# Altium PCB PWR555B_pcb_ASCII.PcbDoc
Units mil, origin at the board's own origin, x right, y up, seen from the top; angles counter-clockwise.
Board outline 3000 x 3000 mil, 4 copper layers (Top Layer, MidLayer1, MidLayer2, Bottom Layer), stack 41.2 mil thick; 56 components, 14 nets, 87 pads, 41 vias.
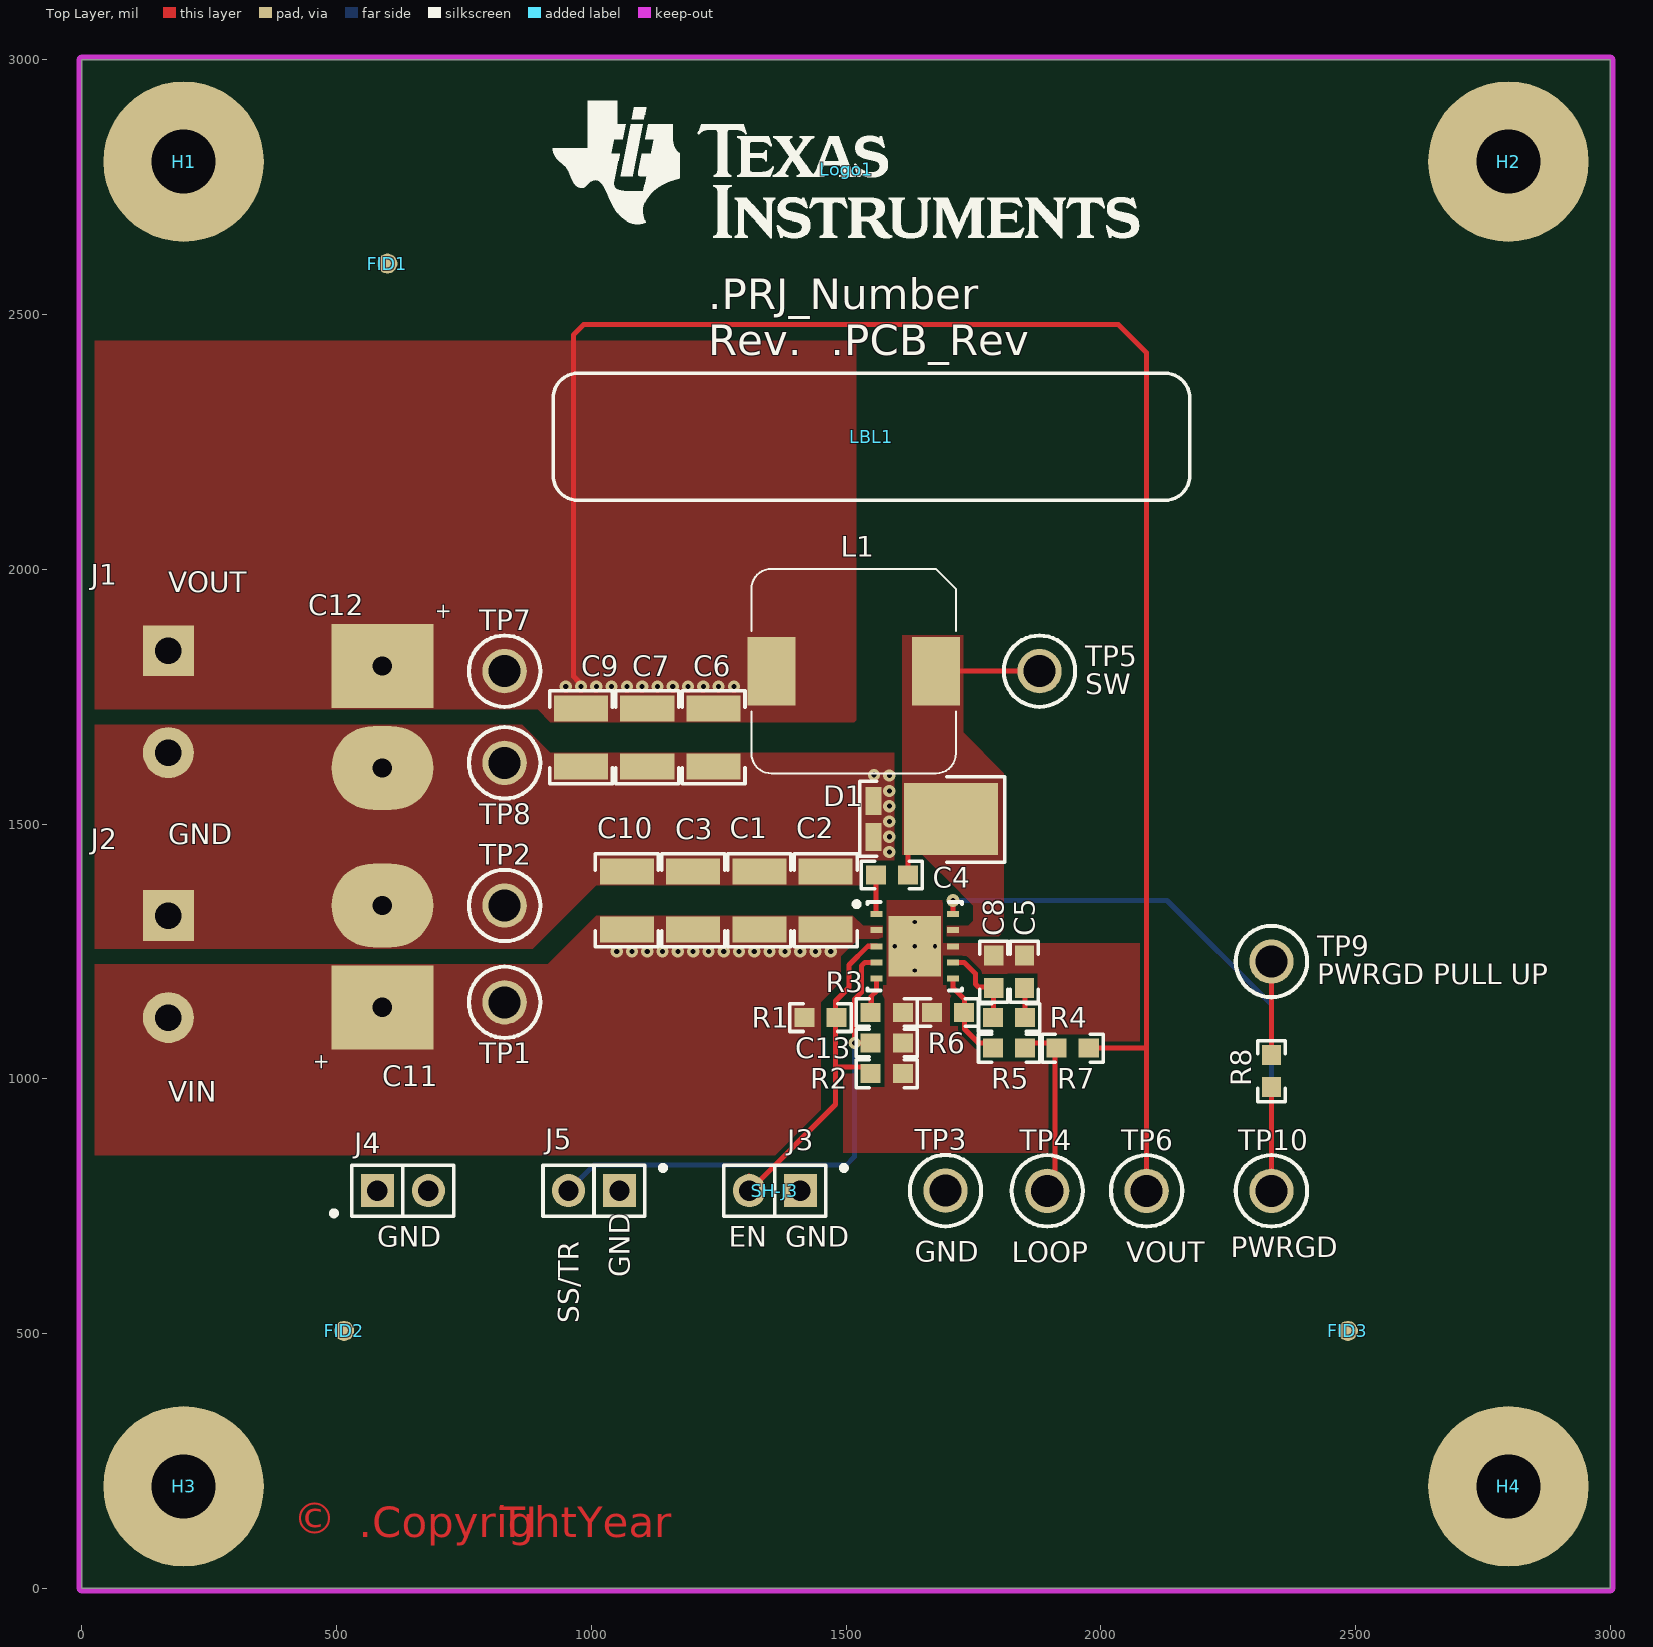
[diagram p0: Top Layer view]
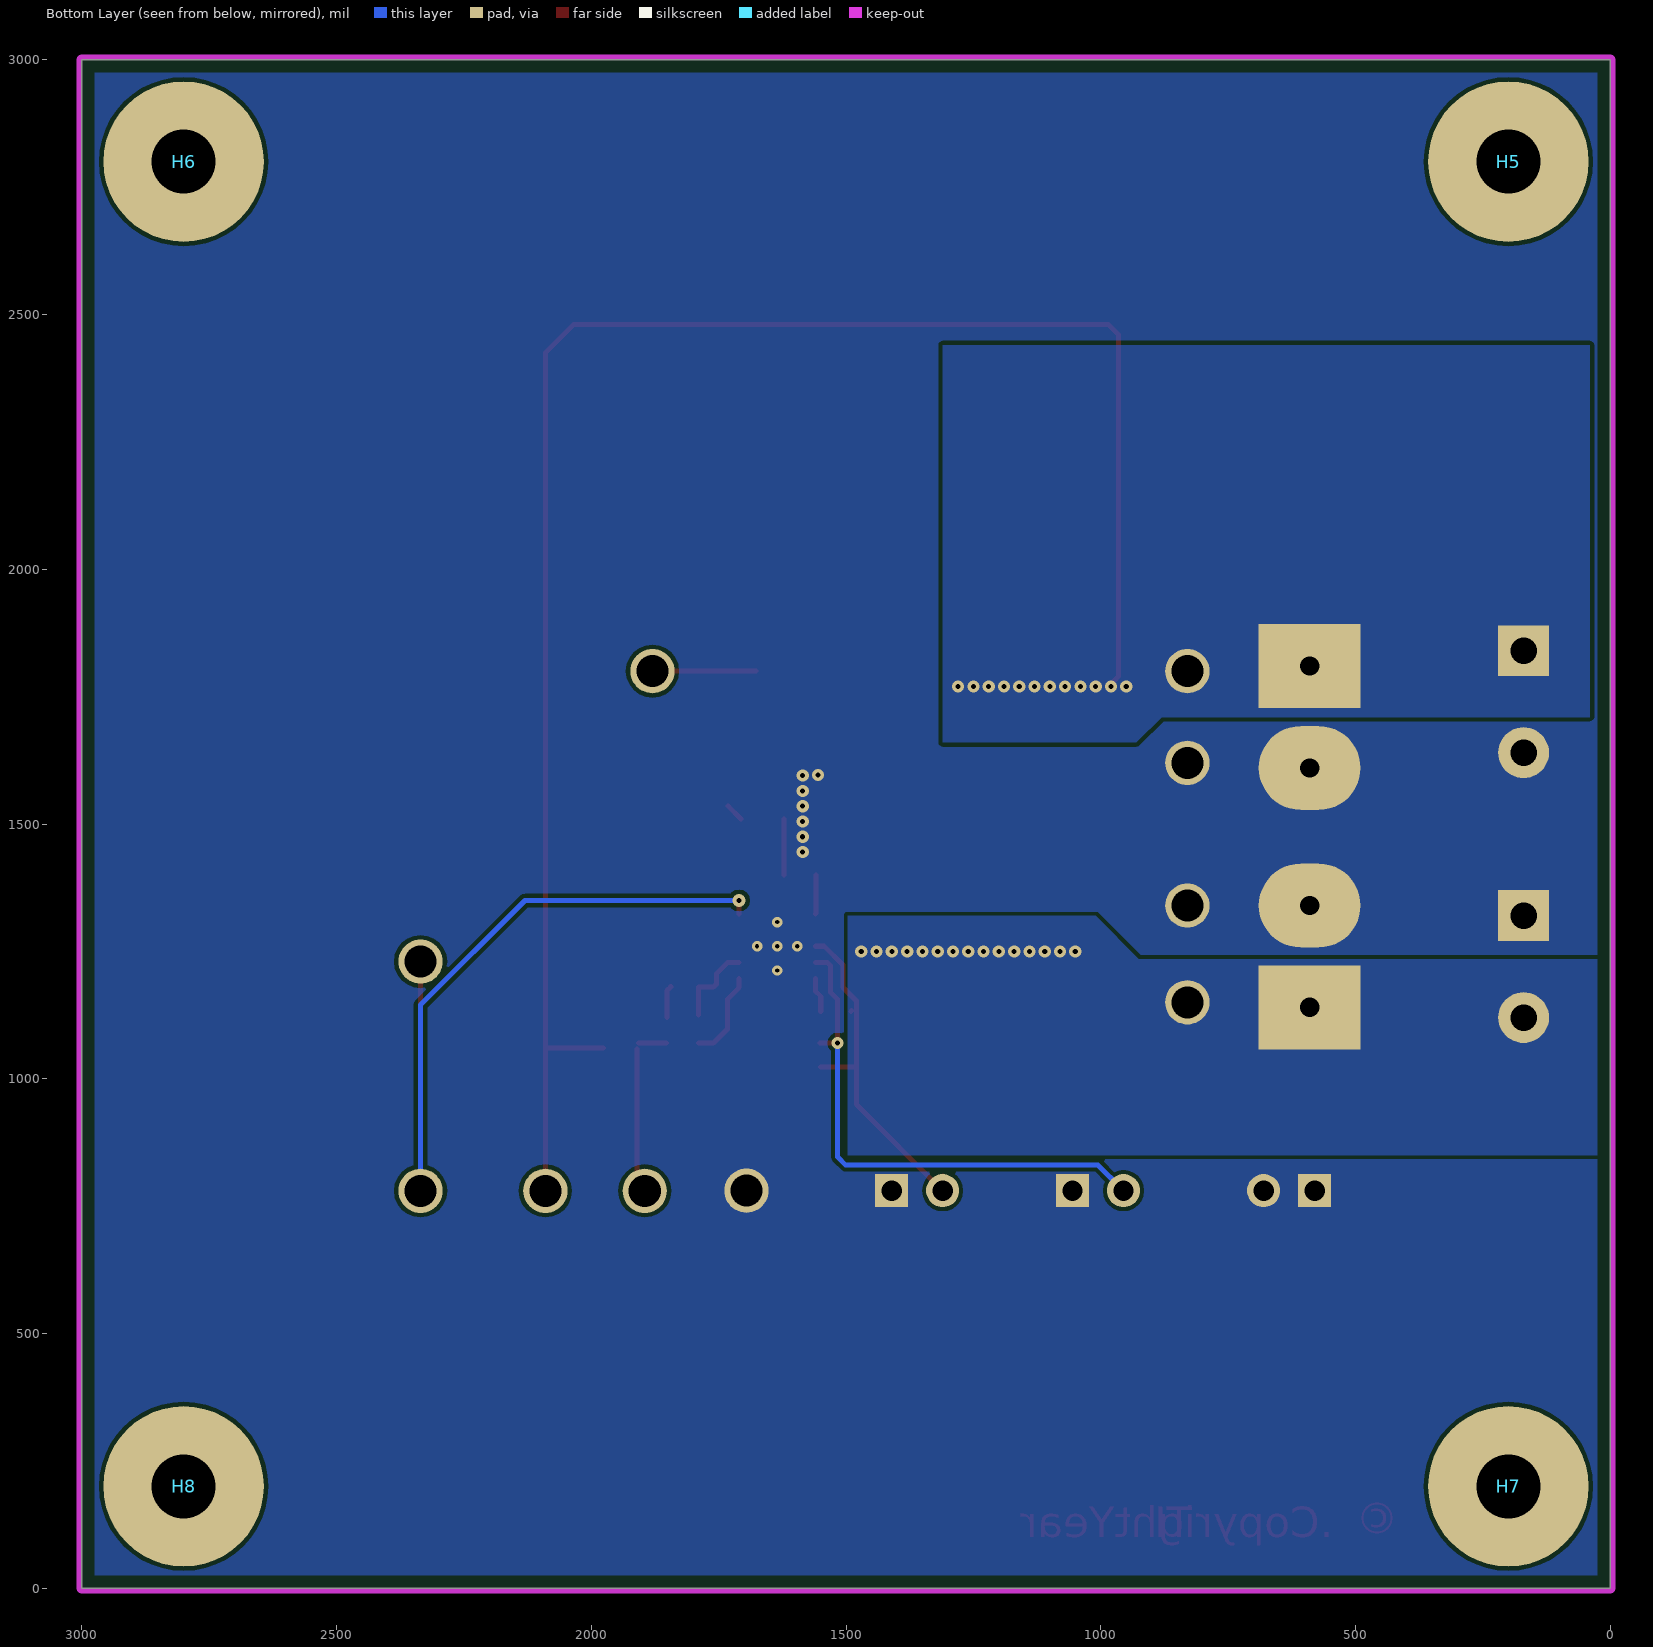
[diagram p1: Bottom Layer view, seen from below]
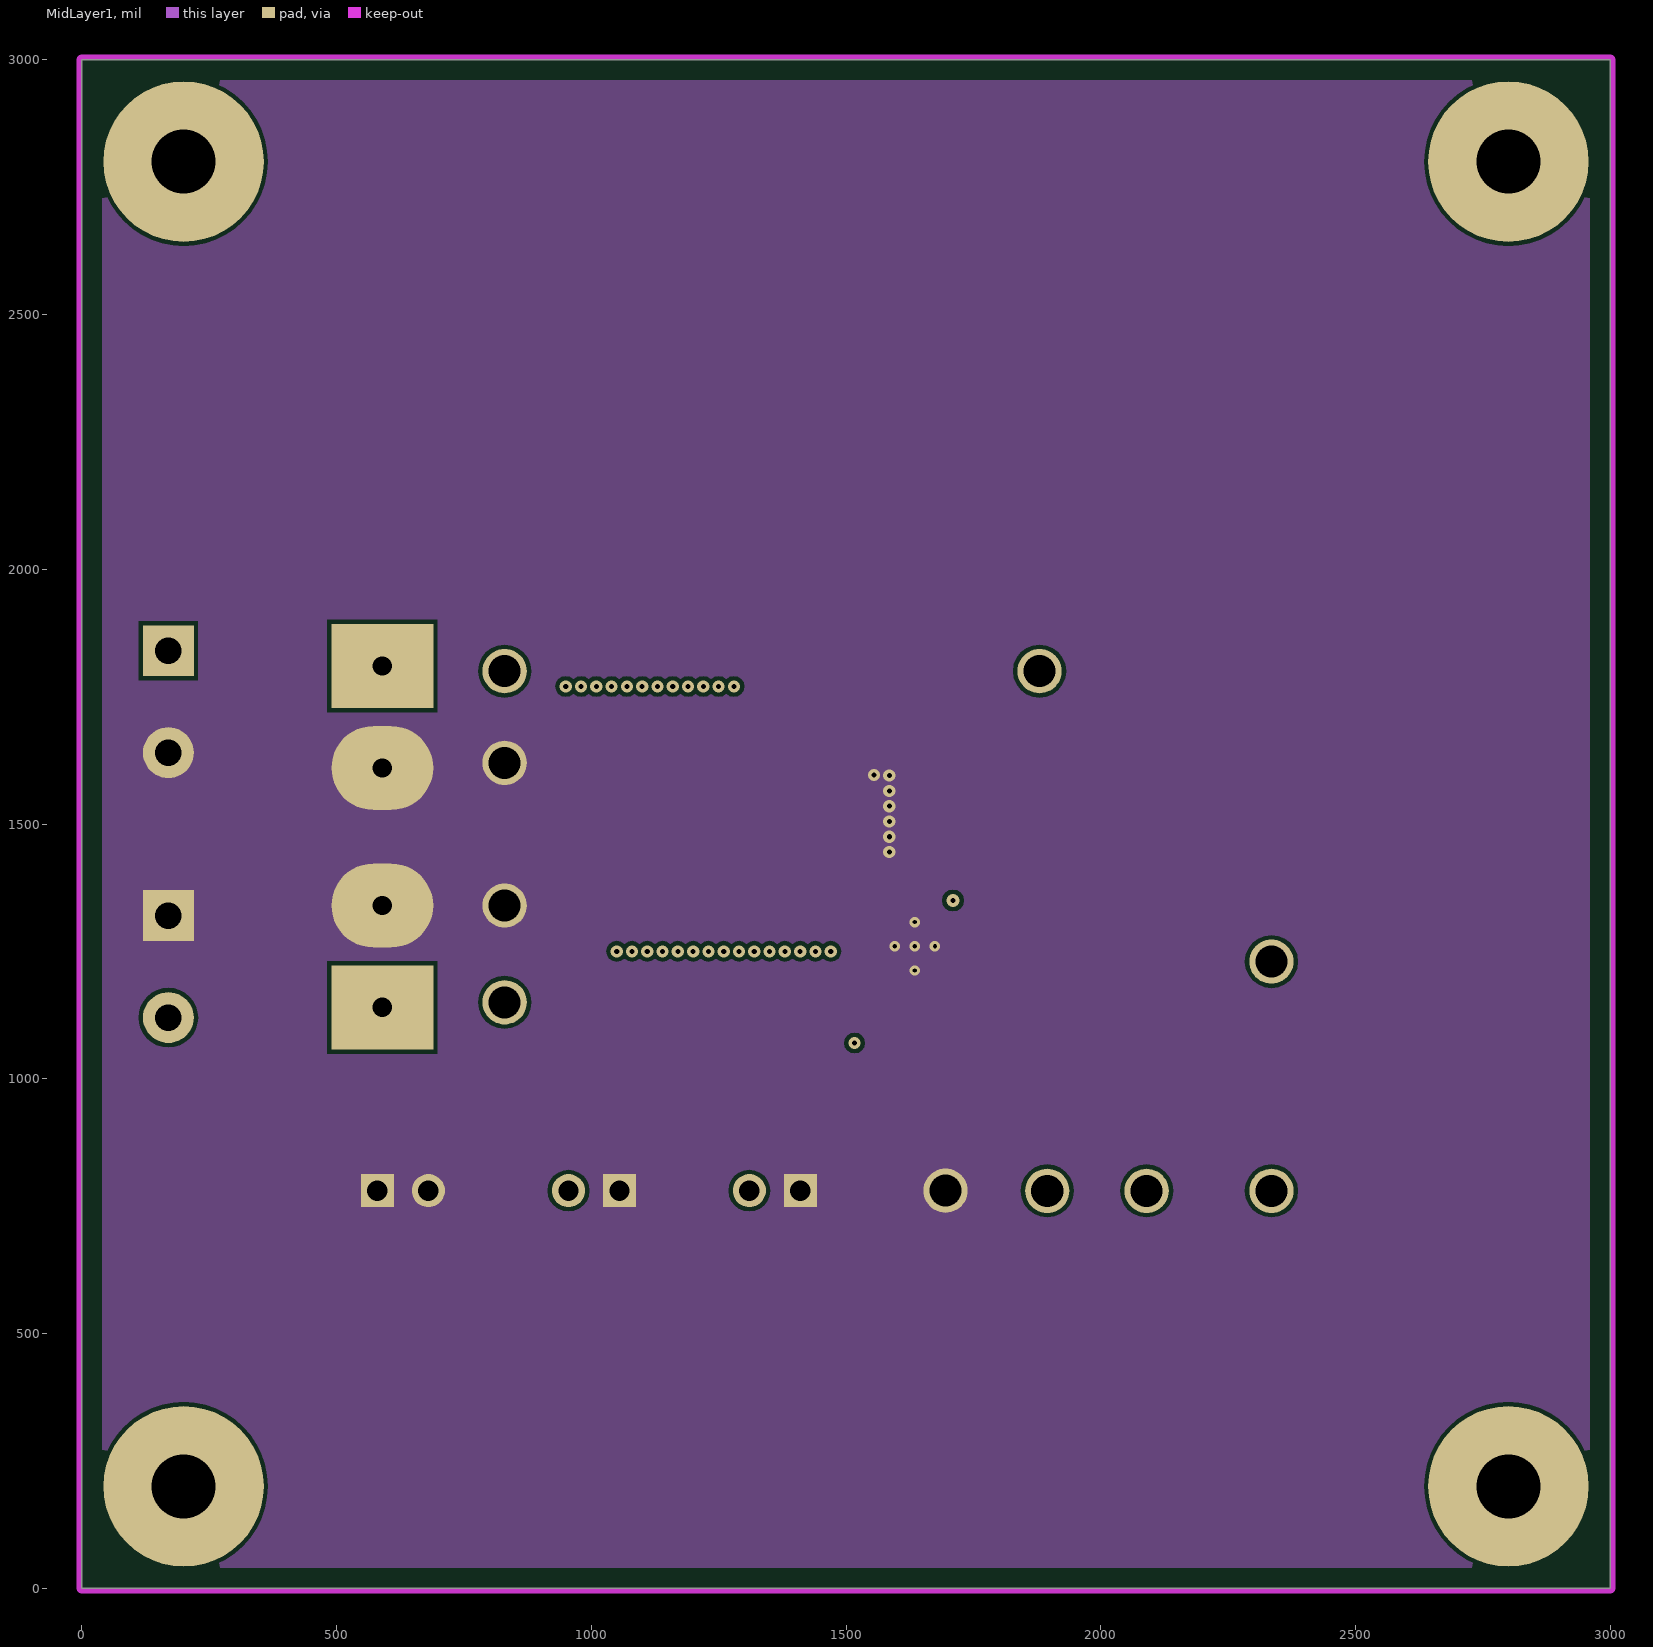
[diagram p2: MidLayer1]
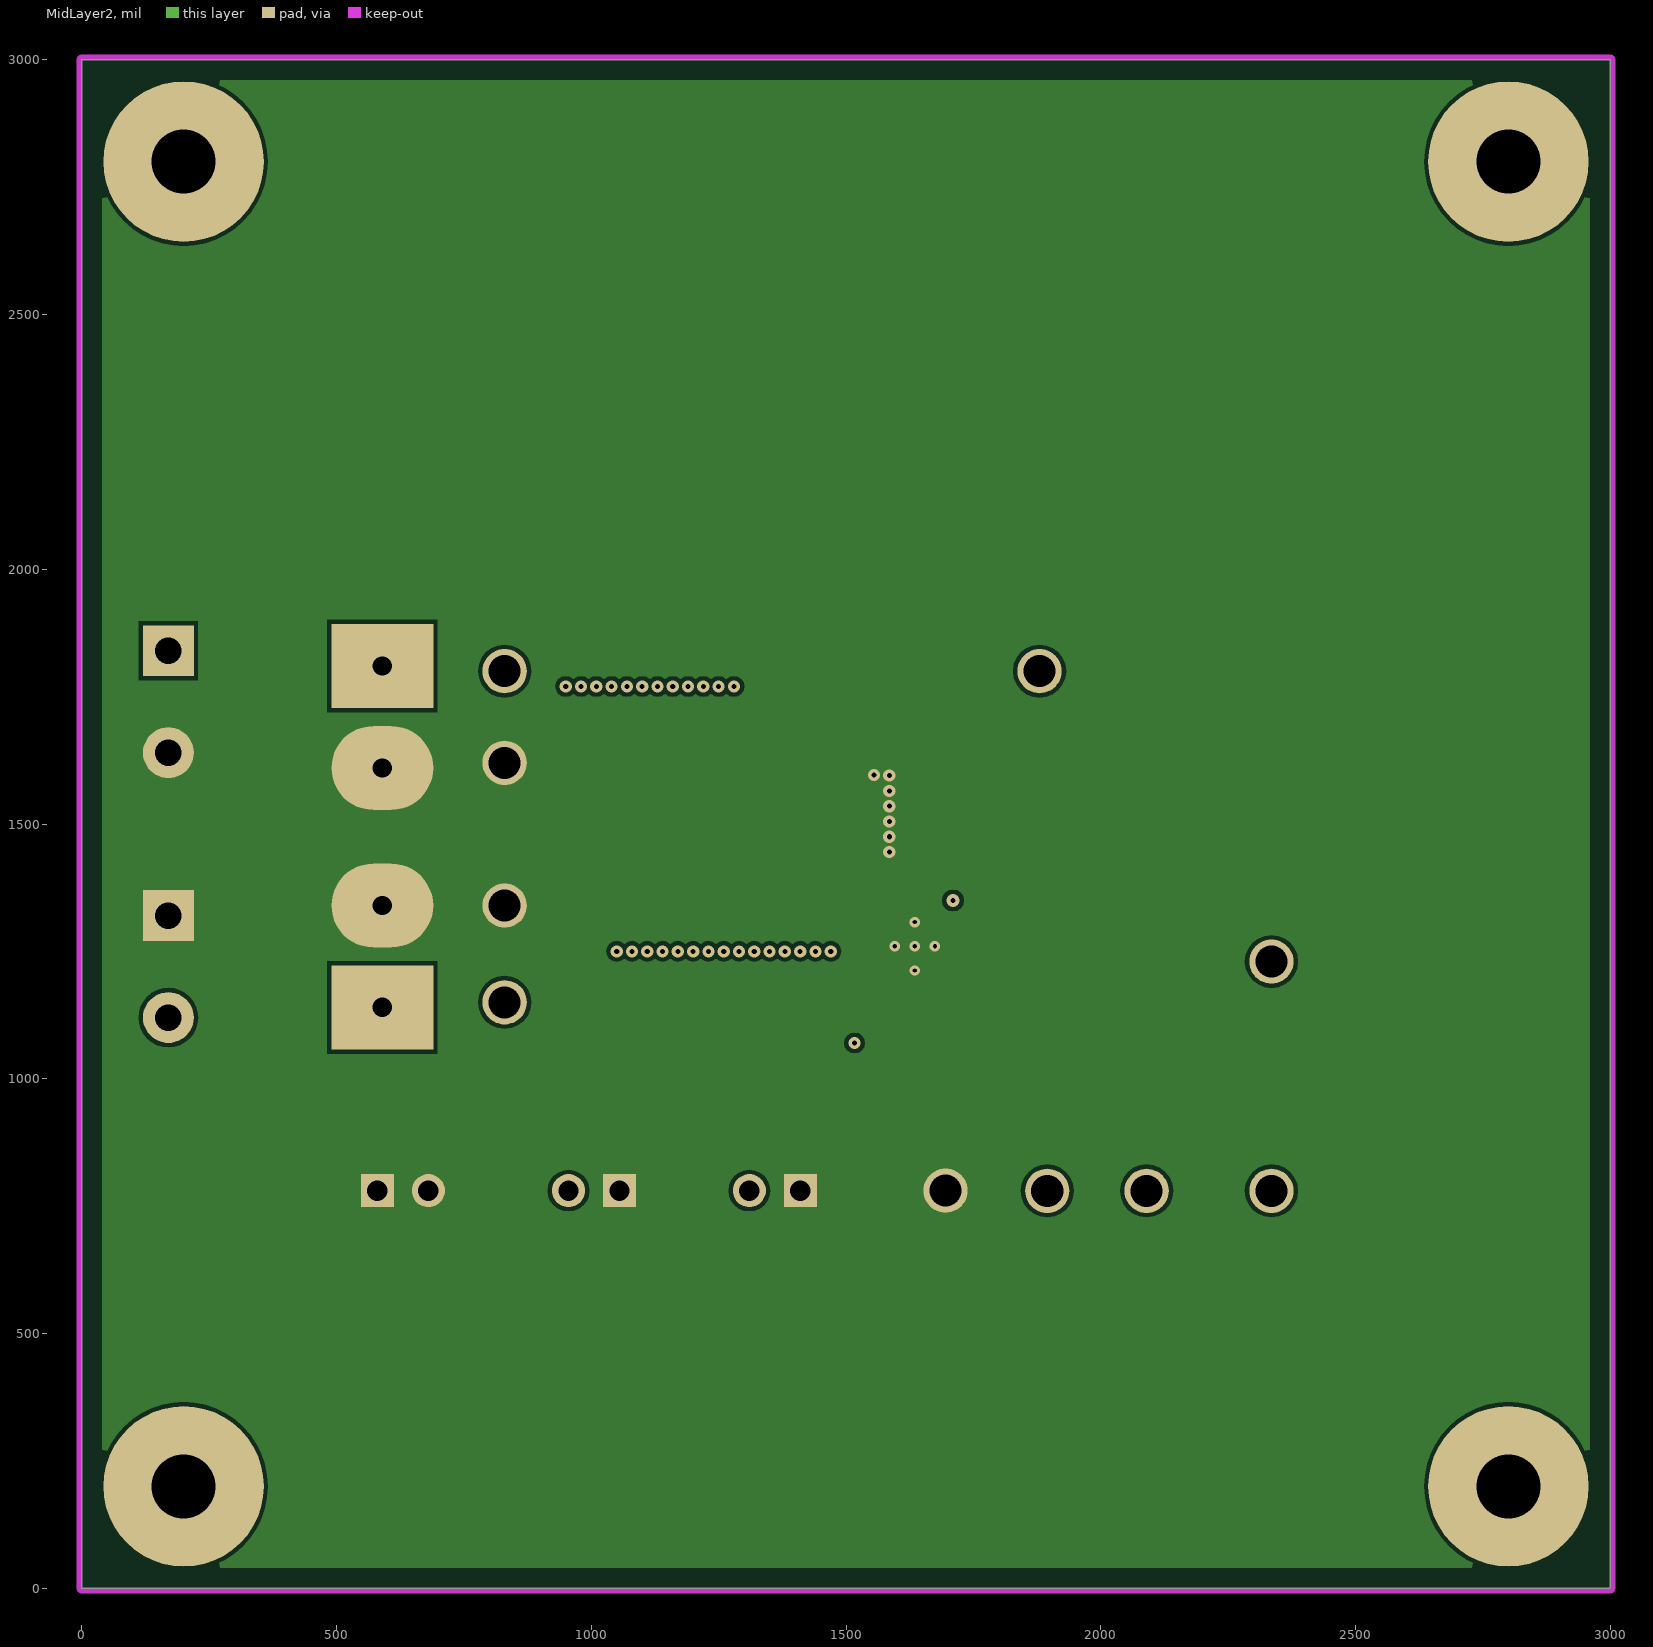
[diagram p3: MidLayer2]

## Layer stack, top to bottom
Top Solder: solder mask 0.4, Solder Resist, Dk 3.5
Top Layer: signal copper 2.8
Dielectric1: core 10, FR-4, Dk 4.8
MidLayer1: signal copper 2.8
Dielectric2: prepreg 10, FR-4, Dk 4.8
MidLayer2: signal copper 2.8
Dielectric3: core 10, FR-4, Dk 4.8
Bottom Layer: signal copper 2.8
Bottom Solder: solder mask 0.4, Solder Resist, Dk 3.5

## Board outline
0,0 3000,0 3000,3000 0,3000

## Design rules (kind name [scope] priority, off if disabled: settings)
AcuteAngle [All] p1: minimum=4.50000000000000E+0001 checktracksonly=FALSE
AssemblyTestPointUsage [All] p1: valid=2
Clearance Clearance_BoardEdge_MountingHoles [OnCopper and InComponentClass('Mounting Holes') vs IsKeepOut] p1: gap=40
Clearance Clearance_BoardEdge_Poly [OnCopper and InPoly vs IsKeepOut] p2: gap=25
Clearance Clearance_BoardEdge [OnCopper and Not InComponentClass('Logo') and not InComponentClass('FiducialMark') and not InRegion(1000,500,4000,800) vs IsKeepOut] p3: gap=25
Clearance [All] p4: gap=8
ComponentClearance "ComponentClearance_Test points" [InComponentClass('Test Points') vs IsThruComponent] p1: gap=0 collisioncheckmode=3 verticalgap=0 showdistances=FALSE
ComponentClearance ComponentClearance_Shunt [InComponentClass('Header') vs InComponentClass('Shunt')] p2: gap=0 collisioncheckmode=3 verticalgap=0 showdistances=FALSE
ComponentClearance ComponentClearance_Logo [All] p3 off: gap=1 collisioncheckmode=3 verticalgap=1 showdistances=TRUE
ComponentClearance ComponentClearance_ScrewToNut [(HasFootprint('NY PMS 440 0025 PH')) vs (HasFootprint('Keystone_1902C'))] p4: gap=1 collisioncheckmode=3 verticalgap=1 showdistances=TRUE
ComponentClearance ComponentClearance_MountingHoles [InComponentClass('Mounting Holes')] p5: gap=250 collisioncheckmode=3 verticalgap=100000 showdistances=TRUE
ComponentClearance ComponentClearance_SmallPassives [HasFootprint('0201*') or HasFootprint('0402*') or HasFootprint('0508') or HasFootprint('0603*') or HasFootprint('0612') or HasFootprint('0805*') or HasFootprint('0815*') or HasFootprint('0830*') or HasFootprint('1206*') or HasFootprint('1210*') or HasFootprint('1808*') or HasFootprint('1812*') or HasFootprint('1825*') or HasFootprint('2010*') or HasFootprint('2220*') or HasFootprint('2225*') or HasFootprint('2512*') or HasFootprint('2728*') or HasFootprint('3518*') vs HasFootprint('0201*') or HasFootprint('0402*') or HasFootprint('0508') or HasFootprint('0603*') or HasFootprint('0612') or HasFootprint('0805*') or HasFootprint('0815*') or HasFootprint('0830*') or HasFootprint('1206*') or HasFootprint('1210*') or HasFootprint('1808*') or HasFootprint('1812*') or HasFootprint('1825*') or HasFootprint('2010*') or HasFootprint('2220*') or HasFootprint('2225*') or HasFootprint('2512*') or HasFootprint('2728*') or HasFootprint('3518*')] p6: gap=0 collisioncheckmode=3 verticalgap=0 showdistances=TRUE
ComponentClearance ComponentClearance_THtoSMT [IsThruComponent vs IsSMTComponent - Shunt] p7: gap=1 collisioncheckmode=3 verticalgap=100000 showdistances=TRUE
ComponentClearance ComponentClearance_THtoTH [IsThruComponent vs IsThruComponent] p8: gap=1 collisioncheckmode=3 verticalgap=0 showdistances=TRUE
ComponentClearance [All] p9: gap=1 collisioncheckmode=3 verticalgap=1 showdistances=TRUE
DiffPairsRouting [All] p1: maxlimit=100 minlimit=10 mostfreqgap=10 toplayer_minwidth=15 toplayer_maxwidth=15 toplayer_prefwidth=15 midlayer1_minwidth=15 midlayer1_maxwidth=15 midlayer1_prefwidth=15 midlayer2_minwidth=15 midlayer2_maxwidth=15 midlayer2_prefwidth=15 bottomlayer_minwidth=15 bottomlayer_maxwidth=15 bottomlayer_prefwidth=15 maxuncoupledlength=1000
FabricationTestPointUsage TestPointUsage [All] p1: valid=2 allowmultiple=FALSE
FabricationTestpoint Testpoint [All] p1: side=3 testpointundercomponent=TRUE minsize=40 maxsize=100 preferedsize=60 minholesize=0 maxholesize=40 preferedholesize=32 testpointgrid=1 allowsidetop=TRUE allowsidebottom=TRUE usegrid=TRUE gridtolerance=0.01
FanoutControl Fanout_LCC [IsLCC] p1: bgadir=Out bgaviamode=Centered fanoutstyle=Auto fanoutdirection=Alternating viagrid=1 // Fanout_LCC (Default Rule)
FanoutControl Fanout_BGA [IsBGA] p2: bgadir=Out bgaviamode=Centered fanoutstyle=Auto fanoutdirection=Alternating viagrid=1 // Fanout_BGA (Default Rule)
FanoutControl Fanout_Default [All] p4: bgadir=Out bgaviamode=Centered fanoutstyle=Auto fanoutdirection=Alternating viagrid=1 // Fanout_Default (Default Rule)
FanoutControl Fanout_Small [(CompPinCount < 5)] p5: bgadir=Out bgaviamode=Centered fanoutstyle=Auto fanoutdirection=OutThenIn viagrid=1 // Fanout_Small (Default Rule)
HoleSize [All] p1: absolutevalues=TRUE maxlimit=251 minlimit=8 maxpercent=80.000 minpercent=20.000
MinimumAnnularRing [All] p1: minimumring=4
MinimumSolderMaskSliver MinimumSolderMaskSliver_Logo [InComponentClass('Logo') vs InComponentClass('Logo')] p1: minsoldermaskwidth=0.7
MinimumSolderMaskSliver [All] p2: minsoldermaskwidth=5
PlaneConnect [All] p1: planeconnectstyle=Direct reliefexpansion=20 reliefentries=4 reliefconductorwidth=10 reliefairgap=10
PolygonConnect [All] p1: connectstyle=Direct reliefconductorwidth=10 reliefentries=4 polygonreliefangle="90 Angle" airgapwidth=10
RoutingVias [All] p1: holewidth=16 width=34 viastyle="Through Hole" minholewidth=7 minwidth=20 maxholewidth=40 maxwidth=65
SMDToCorner [All] p1: distance=0
SilkToBoardRegionClearance [All] p1 off:
SilkToSilkClearance [All] p1: silktosilkclearance=0
SilkToSolderMaskClearance SilkscreenOverComponentPads [IsPad] p1: minsilkscreentomaskgap=0 clearancetoexposedcopper=TRUE
SolderMaskExpansion [All] p1: expansion=1
UnpouredPolygon [All] p1: allowunpoured=FALSE
Width [All] p1: maxlimit=100 minlimit=6 preferedwidth=10 checkconnectedcopper=TRUE
14 further rules are at their usual default settings.

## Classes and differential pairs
component class "Test Points": TP1 TP2 TP3 TP4 TP5 TP6 TP7 TP8 TP9 TP10
component class Shunt: SH-J3
component class PWR555A_hdwr: FID1 FID2 FID3 H1 H2 H3 H4 H5 H6 H7 H8 LBL1 Logo1 SH-J3 ZZ1 ZZ2 ZZ3 ZZ4
component class PWR555A_sch: C1 C2 C3 C4 C5 C6 C7 C8 C9 C10 C11 C12 C13 D1 J1 J2 J3 J4 J5 L1 R1 R2 R3 R4 R5 R6 R7 R8 TP1 TP2 TP3 TP4 TP5 TP6 TP7 TP8 TP9 TP10
component class AssemblyNote: ZZ1 ZZ2 ZZ3 ZZ4
component class FiducialMark: FID1 FID2 FID3
component class Header: J3 J4 J5
component class Label: LBL1
component class Logo: Logo1
component class "Mounting Holes": H1 H2 H3 H4

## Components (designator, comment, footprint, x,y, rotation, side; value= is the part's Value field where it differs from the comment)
C1 "GRM32ER72A225KA35L" 1210 1330,1350 r90 top
C2 "GRM32ER72A225KA35L" 1210 1460,1350 r90 top
C3 "GRM32ER72A225KA35L" 1210 1200,1350 r90 top
C4 "C0603C104K8RACTU" 0603 1590,1400 r180 top
C5 "C0603C472J5RACTU" 0603 1850,1210 r90 top
C6 "GRM32ER61C476ME15L" 1210 1240,1670 r270 top
C7 "GRM32ER61C476ME15L" 1210 1110,1670 r270 top
C8 "06035A470JAT2A" 0603 1790,1210 r90 top
C9 "GRM32ER61C476ME15L" 1210 980,1670 r270 top
C10 "GRM32ER72A225KA35L" 1210 1070,1350 r90 top
C11 "Engineering Only" C_SM-1210/E_TH-F 590,1140 r90 top
C12 "Engineering Only" C_SM-1210/E_TH-F 590,1810 r270 top
C13 "C0603C103K5RACTU" 0603 1580,1070 r0 top
D1 "PDS760-13" PowerDI5 1630,1510 r0 top
FID1 "Fiducial" Fiducial10-20 600,2600 r0 top
FID2 "Fiducial" Fiducial10-20 515,505 r0 top
FID3 "Fiducial" Fiducial10-20 2485,505 r0 top
H1 "NY PMS 440 0025 PH" "NY PMS 440 0025 PH" 200,2800 r0 top locked
H2 "NY PMS 440 0025 PH" "NY PMS 440 0025 PH" 2800,2800 r0 top locked
H3 "NY PMS 440 0025 PH" "NY PMS 440 0025 PH" 200,200 r0 top locked
H4 "NY PMS 440 0025 PH" "NY PMS 440 0025 PH" 2800,200 r0 top locked
H5 "1902C" Keystone_1902C 200,2800 r180 bottom locked
H6 "1902C" Keystone_1902C 2800,2800 r180 bottom locked
H7 "1902C" Keystone_1902C 200,200 r180 bottom locked
H8 "1902C" Keystone_1902C 2800,200 r180 bottom locked
J1 "TBLK_15A_2X5.1MM" TB_2X5.1MM 170,1840 r270 top
J2 "TBLK_15A_2X5.1MM" TB_2X5.1MM 170,1320 r270 top
J3 "TSW-102-07-G-S" TSW-102-07-G-S 1360.36,780.41 r180 top
J4 "TSW-102-07-G-S" TSW-102-07-G-S 630.36,780.41 r0 top
J5 "TSW-102-07-G-S" TSW-102-07-G-S 1005.36,780.41 r180 top
L1 "7447798720" WE-PDF_1064 1515,1799.99 r180 top
LBL1 "Size: 1.25\" x 0.25\"" Label_1250x250 1550,2260 r180 top
Logo1 "Texas Instruments" TI_Stacked_Overlay_Medium 1500,2785 r0 top
R1 "CRCW0603442KFKEA" 0603 1450,1120 r180 top
R2 "CRCW060390K9FKEA" 0603 1580,1010 r180 top
R3 "CRCW0603243KFKEA" 0603 1580,1130 r180 top
R4 "CRCW060316K9FKEA" 0603 1820,1120 r180 top
R5 "CRCW060353K6FKEA" 0603 1820,1060 r0 top
R6 "CRCW060310K2FKEA" 0603 1700,1130 r0 top
R7 "CRCW060349R9FKEA" 0603 1945,1060 r0 top
R8 "CRCW06031K00FKEA" 0603 2335,1015 r90 top
SH-J3 "SNT-100-BK-G" SNT-100-BK-G 1360,780 r180 top
TP1 "5010" Keystone5010 830,1150 r0 top
TP2 "5011" Keystone5011 830,1340 r0 top
TP3 "5011" Keystone5011 1695.36,780.41 r0 top
TP4 "5013" Keystone5013 1895,780 r0 top
TP5 "5014" Keystone5014 1879.87,1800 r0 top
TP6 "5010" Keystone5010 2090,780 r0 top
TP7 "5010" Keystone5010 830,1800 r0 top
TP8 "5011" Keystone5011 830,1620 r0 top
TP9 "5010" Keystone5010 2335,1230 r90 top
TP10 "5014" Keystone5014 2335,780 r90 top
ZZ1 "This Assembly Note is for PCB labels only" AssemblyNoteLabel 185,3938 r0 top
ZZ2 "These assemblies are ESD sensitive, ESD precautions shall be observed." AssemblyNote 185,3829.11 r0 top
ZZ3 "These assemblies must be clean and free from flux and all contaminants. Use of no clean flux is not acceptable." AssemblyNote 185,3740.56 r0 top
ZZ4 "These assemblies must comply with workmanship standards IPC-A-610 Class 2., unless otherwise specified." AssemblyNote 185,3652 r0 top

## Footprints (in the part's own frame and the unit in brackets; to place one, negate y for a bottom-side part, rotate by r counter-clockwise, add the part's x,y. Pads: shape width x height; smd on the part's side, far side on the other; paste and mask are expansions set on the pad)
0603 [mm] "0603 from SM-752 data"
  rect 1x0.95 smd: 1(-0.8,0) 2(0.8,0)
  silkscreen extent -1.52,-0.69 1.52,0.69, body extent -0.87,-0.47 0.87,0.47, height 0.85
1210 [mm] "1210 from SM-752 data"
  rect 1.3x2.7 smd: 1(-1.45,0) 2(1.45,0)
  silkscreen extent -2.32,-1.57 2.32,1.57, body extent -1.7,-1.35 1.7,1.35, height 1.35
AssemblyNote [mil] "Assembly Note"
AssemblyNoteLabel [mil] "Assembly Note for PCB Labels"
C_SM-1210/E_TH-F [mil]
  rect 165x200 hole 38: 1(0,0)
  oval 165x200 hole 38: 2(200,0)
Fiducial10-20 [mm]
  round 1 smd paste-0.5 mask+0.5: 1(0,0)
Keystone5010 [mil] "Keystone Multipurpose loops"
  round 87 hole 63: 1(0,0)
  silkscreen extent -70,-70 70,70, body extent -63,-63 63,62, height 319
Keystone5011 [mil] "Keystone Multipurpose loops"
  round 87 hole 63: 1(0,0)
  silkscreen extent -70,-70 70,70, body extent -63,-63 63,62, height 319
Keystone5013 [mil] "Keystone Multipurpose loops"
  round 87 hole 63: 1(0,0)
  silkscreen extent -70,-70 70,70, body extent -63,-63 63,62, height 319
Keystone5014 [mil] "Keystone Multipurpose loops"
  round 87 hole 63: 1(0,0)
  silkscreen extent -70,-70 70,70, body extent -63,-63 63,62, height 319
Keystone_1902C [mil] "Hex Standoff, 4-40 threaded, nylon"
  body extent -145,-126 146,126, height 501
Label_1250x250 [mil] "Thermal Transfer Labels"
  round 1 on Mech13: 0(0,0)
  silkscreen extent -625,-125 625,125, body extent -625,-125 625,125, height 1
"NY PMS 440 0025 PH" [mm] "4-40 nylon screw and mounting hole"
  round 8 hole 3.2: 1(0,0)
  body extent -3.3,-3.3 3.3,3.3, height 2.69
PowerDI5 [mm] "Diodes Inc recommended land pattern, ap02001.pdf rev 30"
  rect 0.8x1.4 smd: 1(-1.935,0.9) 2(-1.935,-0.9)
  rect 4.7x3.6 smd: 3(1.935,0)
  silkscreen extent -2.62,-2.16 4.6,2.1, body extent -2.32,-2.03 4.27,2.03, height 1.17
SNT-100-BK-G [mil] "Samtec STEP model"
  round 1 on Mech3: 0(0,0)
  body extent -100,-50 100,50, height 344
TB_2X5.1MM [mil]
  rect 100x100 hole 52: 1(0,0)
  round 100 hole 52: 2(200,0)
TI_Stacked_Overlay_Medium [mil]
  silkscreen extent -576,-136 576,134
TSW-102-07-G-S [mm] "Samtec 100mil, 1x2, 230 mil above insulator"
  rect 1.65x1.65 hole 1.016 mask+0: 1(-1.27,0)
  round 1.65 hole 1.016 mask+0: 2(1.27,0)
  silkscreen extent -3.57,-1.27 2.54,1.27, body extent -2.54,-1.27 2.54,1.27, height 8.38
WE-PDF_1064 [mm] "WERTH"
  rect 2.4x3.4 smd: 1(-4.1,0) 2(4.1,0)
  silkscreen extent -5.1,-5.1 5.1,5.1, body extent -5.1,-5.1 5.1,5.1, height 6.35

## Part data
C1 C2 C3 C10: "CAP, CERM, 2.2uF, 100V, +/-10%, X7R, 1210"
C4: "CAP, CERM, 0.1uF, 10V, +/-10%, X7R, 0603"
C5: "CAP, CERM, 4700pF, 50V, +/-5%, X7R, 0603"
C6 C7 C9: "CAP, CERM, 47uF, 16V, +/-20%, X5R, 1210"
C8: "CAP, CERM, 47pF, 50V, +/-5%, C0G/NP0, 0603"
C11 C12: library part C-MULTI_1210-F, "Capacitor, Aluminum, vvV, 20%"
C13: "CAP, CERM, 0.01uF, 50V, +/-10%, X7R, 0603"
D1: library part PDS560-13, "Diode, Schottky, 60V, 7A, PowerDI5"
FID1 FID2 FID3: "Fiducial mark.  There is nothing to buy or mount."
H1 H2 H3 H4: "Machine Screw, Round, #4-40 x 1/4, Nylon, Philips panhead"
H5 H6 H7 H8: "Standoff, Hex, 0.5\"L #4-40 Nylon"
J1 J2: "Terminal Block, 2-pin, 15-A, 5.1mm"
J3 J4 J5: "Header, TH, 100mil, 2x1, Gold plated, 230 mil above insulator"
L1: "Inductor, Shielded, Metal Composite, 7.2uH, 6A, 0.0113 ohm, SMD"
LBL1: library part THT-13-457-10, "Thermal Transfer Printable Labels, 1.250\" W x 0.250\" H - 10,000 per roll"
Logo1: library part TI_Logo, "Texas Instrument Corporate Signature"
R1: "RES, 442k ohm, 1%, 0.1W, 0603"
R2: "RES, 90.9k ohm, 1%, 0.1W, 0603"
R3: "RES, 243k ohm, 1%, 0.1W, 0603"
R4: "RES, 16.9k ohm, 1%, 0.1W, 0603"
R5: "RES, 53.6k ohm, 1%, 0.1W, 0603"
R6: "RES, 10.2k ohm, 1%, 0.1W, 0603"
R7: "RES, 49.9 ohm, 1%, 0.1W, 0603"
R8: "RES, 1.00k ohm, 1%, 0.1W, 0603"
SH-J3: "Shunt, 100mil, Gold plated, Black"
TP1 TP6 TP7: "Test Point, TH, Multipurpose, Red"
TP2 TP3 TP8: "Test Point, TH, Multipurpose, Black"
TP4: "Test Point, TH, Multipurpose, Orange"
TP5 TP10: "Test Point, TH Multipurpose, Yellow"
TP9: "Test Point, Multipurpose, Red, TH"
ZZ1: library part AssemblyNoteLabel
ZZ2 ZZ3 ZZ4: library part AssemblyNote

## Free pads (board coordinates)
  rect 23.62x11.81 smd mask+2: 1(1560.2,1322.99) 2(1560.2,1291.5) 3(1560.2,1260) 4(1560.2,1228.5) 5(1560.2,1197.01) 6(1709.8,1197.01) 7(1709.8,1228.5) 8(1709.8,1260) 9(1709.8,1291.5) 10(1709.8,1322.99)
  rect 102.36x118.11 smd paste-51.18 mask+2: 11(1635,1260)

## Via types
v1: diameter 24/24/24/24 (per signal layer), hole 10, Top Layer to Bottom Layer, tented both sides, 35 vias
v2: diameter 20, hole 8, Top Layer to Bottom Layer, tented both sides, 5 vias
v3: diameter 26/26/26/26 (per signal layer), hole 10, Top Layer to Bottom Layer, tented both sides, 1 vias

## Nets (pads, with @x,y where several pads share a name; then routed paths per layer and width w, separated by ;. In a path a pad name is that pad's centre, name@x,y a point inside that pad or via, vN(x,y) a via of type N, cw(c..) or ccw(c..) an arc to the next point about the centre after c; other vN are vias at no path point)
FB: pad.6 R5.1 R6.2 | length 177.3
  Top Layer w10: pad.6 1709.8,1178.74 1732.5,1156.05 1732.5,1097.5 1760,1070 R5.1@1789.5,1070
GND: C1.2 C2.2 C3.2 C5.2 C6.2 C7.2 C8.2 C9.2 C10.2 C11.2 C12.2 C13.2 D1.1 D1.2 J1.2 J2.1 J3.1 J4.1 J4.2 J5.1 pad.8 pad.11 R2.1 R3.1 R6.1 TP2.1 TP3.1 TP8.1
  other v1: 1585,1445 1585,1475 1585,1505 1585,1535 1585,1565 1585,1595 1555,1595.91
  other v2: 1635,1212.76 1595.63,1260 1635,1260 1674.37,1260 1635,1307.24
NetC1_1: C1.1 C2.1 C3.1 C10.1 C11.1 J2.2 pad.2 R1.2 TP1.1
  other v1: 1050,1250 1080,1250 1110,1250 1140,1250 1170,1250 1200,1250 1230,1250 1260,1250 1290,1250 1320,1250 1350,1250 1380,1250 1410,1250 1440,1250 1470,1250
NetC4_1: C4.1 D1.3 L1.1 pad.9 TP5.1 | length 348.8
  Top Layer w10: C4.1 D1.3@1621.5,1510 ; L1.1 TP5.1 ; D1.3 D1.3@1731.18,1535
NetC4_2: C4.2 pad.1 | length 77.7
  Top Layer w10: C4.2 1558.5,1324.68 pad.1
NetC5_1: C5.1 R4.1 | length 63.6
  Top Layer w10: C5.1@1844,1180.5 1851.5,1173.01 R4.1
NetC6_1: C6.1 C7.1 C9.1 C12.1 J1.1 L1.2 R7.2 TP6.1 TP7.1 | length 3614.5
  Top Layer w10: v1@975.19,1779.81 965,1790 965,2460 985,2480 2035,2480 2090,2425 2090,1060 ; R7.2 2090,1060 ; TP6.1@2089,781 TP6.1 TP6.1@2090,790 ; TP6.1@2100,780 TP6.1@2090,790 ; TP6.1@2090,790 2090,1060
  other v1: 950,1770 980,1770 1010,1770 1040,1770 1070,1770 1100,1770 1130,1770 1160,1770 1190,1770 1220,1770 1250,1770 1280,1770
NetC8_1: C8.1 pad.7 R4.2 | length 166.7
  Top Layer w10: pad.7 1731.5,1228.5 1754,1206 1754,1185.73 1759.73,1180 1789.5,1180 R4.2@1789.5,1125
NetJ3_2: J3.2 pad.3 R1.1 R2.2 | length 716.8
  Top Layer w10: J3.2@1309.86,808.92 J3.2@1324.36,794.41 ; J3.2@1331.36,787.41 J3.2@1324.36,794.41 ; R1.1@1489,1133.5 R1.1@1490.5,1132 ; R2.2@1549.5,1023 1482.5,1023 1479.5,1020 ; pad.3 1542.92,1260 1506,1223.08 1506,1179.2 1479.5,1152.7 1479.5,1020 ; J3.2@1324.36,794.41 J3.2 1479.5,949.55 1479.5,1020
NetR3_2: pad.5 R3.2 | length 69.4
  Top Layer w10: R3.2@1549.5,1132 1549.5,1161.7 1560.2,1172.4 pad.5
NetR5_2: R5.2 R7.1 TP4.1 | length 340.3
  Top Layer w10: R5.2@1852.5,1070 R7.1@1907.5,1070 ; TP4.1@1894.87,779.5 1910,794.63 R7.1@1910,1058.5
NetR8_1: pad.10 R8.1 TP10.1 | length 1305.5
  Top Layer w10: pad.10 v3@1709.8,1349.8 ; TP10.1@2335,779.87 R8.1
  Bottom Layer w10: v3(1710,1350) 2130,1350 2335,1145 TP10.1@2335,779.87
NetR8_2: R8.2 TP9.1 | length 183.5
  Top Layer w10: R8.2 TP9.1
SS/TR: C13.1 J5.2 pad.4 | length 1044.7
  Top Layer w10: C13.1@1550.5,1070 C13.1 v1(1516.82,1070) 1516.82,1156.09 1530.09,1169.35 1530.09,1221.09 1537.5,1228.5 pad.4
  Bottom Layer w10: J5.2@950.36,785.41 960.36,785.41 1005.36,830.41 1500.41,830.41 1516.82,846.82 v1@1516.82,1076.18
pads on no net: FID1.1 FID2.1 FID3.1 H1.1 H2.1 H3.1 H4.1 LBL1.0 SH-J3.0

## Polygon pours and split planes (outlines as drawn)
NetC1_1 on Bottom Layer "Bottom Layer-VIN" (solid, remove dead copper, pour order 14): -5,1235 925,1235 1010,1320 1496.43,1320 1496.43,850 -5,850
GND on Bottom Layer "Bottom Layer-GND" (solid, pour order 15): 0,3005 0,0 3005,0 3005,3000
NetC6_1 on Bottom Layer "Bottom Layer-VOUT" (solid, remove dead copper, pour order 13): 40,2440 1310,2440 1310,1660 930,1660 880,1710 40,1710
GND on MidLayer2 "MidLayer2-GND" (solid, remove dead copper, pour order 18): 40,2960 40,40 2960,40 2960,2960
GND on MidLayer1 "MidLayer1-GND" (solid, remove dead copper, pour order 17): 40,2960 2960,2960 2960,40 40,40
NetC4_1 on Top Layer "Top Layer-SW" (solid, remove dead copper, pour order 12): 1695,1280 1800,1280 1810,1290 1810,1600 1730,1680 1730,1870 1610,1870 1610,1440 1650,1440 1750,1340 1750,1310 1740,1300 1695,1300
NetC6_1 on Top Layer "Top-VOUT" (solid, remove dead copper, pour order 16): -5.26,1725 895,1725 920,1700 1520.04,1700 1519.8,2448.62 -5.26,2448.62
NetC1_1 on Top Layer "Top Layer-VIN" (solid, remove dead copper, pour order 11): 0,1225 915,1225 1010,1320 1513.64,1320 1533.64,1300 1575,1300 1575,1275 1525,1275 1490,1240 1490,1190 1450,1150 1450,850 0,850
GND on Top Layer "Top Layer-GND" (solid, remove dead copper, pour order 10): 10,1695 865,1695 920,1640 1595,1640 1595,1428.54 1530,1428.54 1530,1381.32 1580,1381.3 1580,1350 1690,1350 1690,1266.2 2095,1266.2 2095,855 1495,855 1495,1235 1580,1235 1580,1380 1010,1380 885,1255 10,1255

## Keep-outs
Keep-Out Layer:
  lines w10: -5,0 ccw(c0,0) 0,-5 ; -5,0 ccw(c0,0) 0,-5 ; -5,0 -5,3000 ; -5,3000 cw(c0,3000) 0,3005 ; -5,3000 cw(c0,3000) 0,3005 ; 0,-5 3000,-5 ; 0,3005 3000,3005 ; 3000,-5 ccw(c3000,0) 3005,0 ; 3000,-5 ccw(c3000,0) 3005,0 ; 3000,3005 cw(c3000,3000) 3005,3000 ; 3000,3005 cw(c3000,3000) 3005,3000 ; 3005,0 3005,3000
  text ".Layer_Name" at 577,-858.49 h60

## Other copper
Top Layer:
  text ".CopyrightYear" at 544,100 h60
  text "TI" at 820,100 h60
  text "©" at 415,86.48 h105
  text ".Layer_Name" at 577,-858.49 h60
MidLayer1:
  text "MIDLAYER 1" at 645,-860 h60
MidLayer2:
  text "MIDLAYER 2" at 615,-860 h60
Bottom Layer:
  text ".Layer_Name" at 577,-858.49 h60
Multi-Layer:
  text "Multilayer" at 685,-860 h60

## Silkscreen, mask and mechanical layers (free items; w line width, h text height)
Top Overlay:
  circle w9.84: c1520.83,1342.68 r4.92
  lines w7.87: 1542.48,1173.39 1542.48,1177.32 ; 1542.48,1342.68 1542.48,1346.61 ; 1542.68,1173.39 1568.07,1173.39 ; 1542.68,1346.61 1568.07,1346.61 ; 1701.93,1173.39 1727.32,1173.39 ; 1701.93,1346.61 1727.32,1346.61 ; 1727.52,1173.39 1727.52,1177.32 ; 1727.52,1342.68 1727.52,1346.61
  text ".PRJ_Number" at 1230,2510 h60
  text "Rev." at 1230,2420 h60
  text ".PCB_Rev" at 1470,2420 h60
  text "VOUT" at 170,1955 h40
  text "SW" at 1970,1755 h40
  text "GND" at 170,1460 h40
  text "PWRGD PULL UP" at 2425,1185 h40
  text "VIN" at 170,955 h40
  text "GND" at 580.36,670.41 h40
  text "EN" at 1270.36,670.41 h40
  text "GND" at 1380.36,670.41 h40
  text "PWRGD" at 2255,650 h40
  text "GND" at 1635.36,640.41 h40
  text "LOOP" at 1825,640 h40
  text "VOUT" at 2050,640 h40
  text "GND" at 1075.36,610.41 h40 r90
  text "SS/TR" at 975.36,520.41 h40 r90
  text ".Layer_Name" at 577,-858.49 h60
Bottom Overlay:
  text ".Layer_Name" at 577,-858.49 h60
Top Paste:
  rectangle: 1638.94,1204.49 1684.13,1256.06
  region: 1631.06,1256.06 1585.87,1256.06 1585.87,1204.49 1631.06,1204.49
  region: 1631.06,1315.51 1585.87,1315.51 1585.87,1263.94 1631.06,1263.94
  rectangle: 1638.94,1263.94 1684.13,1315.51
  text ".Layer_Name" at 577,-858.49 h60
Bottom Paste:
  text ".Layer_Name" at 577,-858.49 h60
Top Solder:
  text ".Layer_Name" at 577,-858.49 h60
  text ".Layer_Name" at 577,-858.49 h60
Bottom Solder:
  text ".Layer_Name" at 577,-858.49 h60
Drill Guide:
  text ".Layer_Name" at 577,-858.49 h60
M1 Board Outline:
  the board outline again, w10
  text ".Layer_Name" at 577,-858.49 h60
M2 Board Dimensions:
  rectangle: -0.5,-285.5 124.5,-160.5
  rectangle: 124.5,-410.5 499.5,-285.5
  lines w7: -0.5,-285.5 999.5,-285.5 ; 124.5,-410.5 124.5,-160.5 ; 249.5,-410.5 249.5,-160.5 ; 499.5,-410.5 499.5,-160.5 ; 749.5,-410.5 749.5,-160.5 ; -0.5,-410.5 999.5,-410.5 999.5,-160.5 -0.5,-160.5 -0.5,-410.5
  lines w10: -0.5,-475.5 -0.5,-455.5 ; 59.5,-485.5 -0.5,-465.5 ; 59.5,-445.5 -0.5,-465.5 ; 223.58,-465.5 -0.5,-465.5 ; 775.42,-465.5 999.5,-465.5 ; 939.5,-485.5 999.5,-465.5 ; 939.5,-445.5 999.5,-465.5 ; 999.5,-475.5 999.5,-455.5
  text "1000 (mil)" at 233.58,-501.49 h60
  text ".Layer_Name" at 577,-858.49 h60
M3 3D STEP Top:
  text ".Layer_Name" at 577,-858.49 h60
M4 3D STEP Bottom:
  text ".Layer_Name" at 577,-858.49 h60
M5 Assembly Top:
  circle w3.94: c1572.01,1322.99 r7.87
  lines w3.94: 1554.29,1179.29 1715.71,1179.29 1715.71,1340.71 1554.29,1340.71 1554.29,1179.29
  lines w7: 6324,715.5 7449,715.5 ; 6324,845.5 7449,845.5 ; 6324,965.5 7449,965.5 ; 6324,1088 7446.5,1088 ; 6639,600 6639,1208 ; 7024,1208 6324,1208 ; 6324,1208 6324,600 7449,600 7449,1208 6324,1208
  lines w10: -292,-930.17 6308,-930.17 ; -292,-726.83 6310,-726.83 ; -292,-523.5 -292,-1133.5 3713,-1133.5 6310,-1133.5 6310,-523.5 -291.5,-523.5 -291.5,-1133.5 1284,-1133.5 ; 2173,-1133.5 2173,-523.5 ; 3440,-726.83 3440,-523.5 ; 4280,-726.83 4280,-523.5 ; 4902,-1140 4902,-937.17
  text ".Designator" at 1579.88,1244.25 h30
  text "TABLE 1" at 6711.5,1243 h40
  text "Variant" at 6349,1133 h40
  text "Label text" at 6784,1133 h40
  text "001" at 6416.5,1013 h40
  text "TPS54561EVM-555" at 6694,1010.5 h40
  text "002" at 6416.5,888 h40
  text "TPS54541EVM-555" at 6689,885.5 h40
  text "003" at 6416.5,763 h40
  text "TPS54541EVM-555" at 6694,760.5 h40
  text "004" at 6416.5,638 h40
  text "TPS54541EVM-555" at 6689,635.5 h40
  text "COMPONENTS MARKED 'DNP' SHOULD NOT BE POPULATED, AND MAY NOT BE IN BILL OF MATERIALS" at 1153.5,-318.5 h60
  text "ASSEMBLY VARIANT:" at 1153,-434 h60
  text ".VariantName" at 2189,-434 h60
  text "PCB VIEWED FROM TOP SIDE" at -228.5,-655.67 h60
  text "BOARD #:" at 2248,-655.67 h60
  text ".PRJ_Number" at 2793.5,-655.67 h60
  text "REV:" at 3638,-655.67 h60
  text ".PCB_Rev" at 3929.5,-655.67 h60
  text "SVN REV:" at 4476,-655.67 h60
  text ".VersionControl_RevNumber" at 4982,-655.67 h60
  text "IGNORE ->" at -228.5,-858.49 h60
  text "PLOT NAME =" at -228.5,-1064.34 h60
  text ".plot_File_Name" at 577,-1064.34 h60
  text "GENERATED    :" at 2250,-1064.34 h60
  text ".Print_Date" at 3119.5,-1064.34 h60
  text ".Print_Time" at 3848.5,-1064.34 h60
  text "TEXAS INSTRUMENTS" at 5113,-1064.34 h60
M6 Assembly Bottom:
  lines w10: -292.5,-727.33 6309.5,-727.33 ; -290.5,-930.67 6309.5,-930.67 ; 1115.5,-1140.5 1115.5,-937.67 ; 1737.5,-727.33 1737.5,-524 ; 2577.5,-727.33 2577.5,-524 ; 3844.5,-1134 3844.5,-524 ; 4733.5,-1134 6309,-1134 6309,-524 -292.5,-524 -292.5,-1134 2304.5,-1134 6309.5,-1134 6309.5,-524
  text "COMPONENTS MARKED 'DNP' SHOULD NOT BE POPULATED, AND MAY NOT BE IN BILL OF MATERIALS" at 6102,-318 h60
  text ".VariantName" at 5058,-434 h60
  text "ASSEMBLY VARIANT:" at 6097,-434 h60
  text ".VersionControl_RevNumber" at 1035.5,-656.17 h60
  text "SVN REV:" at 1541.5,-656.17 h60
  text ".PCB_Rev" at 2088,-656.17 h60
  text "REV:" at 2379.5,-656.17 h60
  text ".PRJ_Number" at 3224,-656.17 h60
  text "BOARD #:" at 3769.5,-656.17 h60
  text "PCB VIEWED FROM BOTTOM SIDE" at 6246,-656.17 h60
  text "IGNORE ->" at 2547.85,-858.49 h60
  text "TEXAS INSTRUMENTS" at 904.5,-1064.84 h60
  text ".Print_Time" at 2169,-1064.84 h60
  text ".Print_Date" at 2898,-1064.84 h60
  text "GENERATED    :" at 3767.5,-1064.84 h60
  text ".plot_File_Name" at 5440.5,-1064.84 h60
  text "PLOT NAME =" at 6246,-1064.84 h60
M9 Title Sheet:
  drawing of 57 lines, arcs and shapes, not listed
  text "1" at 739.84,8036.5 h70
  text "2" at 3235.5,8036.5 h70
  text "3" at 5724.84,8036.5 h70
  text "4" at 8231.51,8036.5 h70
  text "5" at 10730.5,8036.5 h70
  text "6" at 13235.5,8036.5 h70
  text "A" at -416.5,6893.5 h70
  text "A" at 14383.5,6893.5 h70
  text "B" at -416.5,4513.5 h70
  text "B" at 14383.5,4513.5 h70
  text "C" at -416.5,2138.5 h70
  text "C" at 14383.5,2138.5 h70
  text "PROJECT TITLE:" at 11343.5,277.5 h45
  text ".PRJ_Title" at 11393.5,144.17 h70
  text "DESIGNED FOR:" at 11343.5,-23.5 h45
  text ".PRJ_Customer" at 11393.5,-163.5 h70
  text "D" at -416.5,-231.5 h70
  text "D" at 14383.5,-231.5 h70
  text "FILE NAME:" at 11343.5,-323.5 h45
  text ".PCB_File_Name_No_Path" at 11393.5,-443.5 h70
  text "Texas Instruments (TI) and/or its licensors do not warrant the accuracy or completeness of this specification" at 6374,-605.34 h45
  text "ENGINEER:" at 11343.5,-613.5 h45
  text "LAYOUT BY:" at 12848.5,-613.5 h45
  text "or any information contained therein. TI and/or its licensors do not warrant that this design will meet" at 6329.01,-718 h45
  text ".PRJ_Engineer" at 11393.5,-768.49 h70
  text ".PCB_Layout" at 12899,-768.49 h70
  text "the specifications, will be suitable for your application or fit for any particular purpose, or will operate in" at 6329.01,-830.67 h45
  text ".Layer_Name" at 577,-858.49 h60
  text "ALTIUM DESIGNER VERSION:" at 12848.5,-923.5 h45
  text "an implementation. TI and/or its licensors do not warrant that the design is production worthy. You should" at 6329.01,-943.33 h45
  text "completely validate and test your design implementation to confirm the system functionality for your application." at 6374,-1056 h45
  text ".print_Scale" at 11393.5,-1056.83 h70
  text ".Application_BuildNumber" at 12899,-1056.83 h70
  text "1" at 739.84,-1263.5 h70
  text "2" at 3235.5,-1263.5 h70
  text "3" at 5724.84,-1263.5 h70
  text "4" at 8231.51,-1263.5 h70
  text "5" at 10730.5,-1263.5 h70
  text "6" at 13235.5,-1263.5 h70
M10 Fab Notes:
  drawing of 203 lines, arcs and shapes, not listed
  text "DESIGN INFORMATION" at 12381.02,6810 h60
  text "(REFER ALSO ARRAY/PANEL PROFILING INFORMATION)" at 12019.46,6648.29 h60
  text "BOARD SIZE" at 11333.46,6644 h60
  text "3000MIL" at 11795.78,6516.18 h60
  text "X" at 12301.46,6516.18 h60
  text "3000MIL" at 12532.78,6516.18 h60
  text "Number of Layers :" at 11736.46,6319 h60
  text "4" at 12831.27,6309 h60
  text "MIN. TRACK WIDTH:" at 11736.46,6180 h60
  text "10" at 12832.7,6180 h60
  text "MIL" at 12987.46,6180 h60
  text "MIN. CLEARANCE:" at 11736.46,6048 h60
  text "8" at 12832.7,6048 h60
  text "MIL" at 12987.46,6048 h60
  text "MIN. VIA PAD SIZE:" at 11736.46,5916 h60
  text "20" at 12802.71,5916 h60
  text "MIL" at 12987.46,5916 h60
  text "0.05mm (2MIL)" at 12431.46,5774.29 h60
  text "MINIMUM ANNULAR RING" at 11407.23,5770 h60
  text "EXTERNAL" at 13139.46,5770 h60
  text "PER" at 11607.23,5652 h60
  text "IPC-D-275 CLASS 2 LEVEL C" at 11827.23,5652 h60
  text "MIL, HOLES" at 13315.46,5539.71 h60
  text "+/-" at 12923,5539 h60
  text "+/-" at 13777,5539 h60
  text "REGISTRATION TOLERANCES:" at 11407.23,5534 h60
  text "METAL" at 12607,5534 h60
  text "5" at 13183.2,5534 h60
  text "3" at 14016.2,5534 h60
  text "MIL" at 14132.46,5534 h60
  text "MATERIAL:" at 11332.46,5324.54 h60
  text "FR-4 High Tg" at 12318.9,5184.21 h60
  text "FR-4" at 11793.46,5175.64 h60
  text "X" at 12165.46,5175.64 h60
  text "OTHER" at 13241.46,5175.64 h60
  text "62 MIL (1.6mm) +/-10%" at 12073.56,5012.92 h60
  text "THICKNESS:" at 11407.23,5008.64 h60
  text "X" at 11945.4,5008.64 h60
  text "OTHER" at 13358.46,5008.64 h60
  text "TOLERANCE:" at 11407.23,4850.64 h60
  text "X" at 12246.53,4850.64 h60
  text "ANSI IPC-6012 TYPE 3 CLASS 2" at 12433.48,4850.64 h60
  text "OTHER +/-" at 12433.46,4694.64 h60
  text "BOW & TWIST:" at 11407.23,4537.64 h60
  text "X" at 12246.53,4537.64 h60
  text "ANSI IPC-6012 TYPE 3 CLASS 2" at 12433.48,4537.64 h60
  text "OTHER +/-" at 12433.46,4379.13 h60
  text "COPPER THICKNESS (FINISHED):" at 11332.46,4243.64 h60
  text "1.4MIL (1oz)" at 12212.46,4090.92 h60
  text "2MIL (1.4oz)" at 12979.46,4090.92 h60
  text "2.8MIL (2oz)" at 13706.46,4090.92 h60
  text "OUTER:" at 11689.46,4086.64 h60
  text "X" at 13580,4085 h60
  text "1.4MIL (1oz)" at 12562.46,3933.92 h60
  text "2.8MIL (2oz)" at 13406.46,3933.92 h60
  text "INNER SIGNAL:" at 11689.46,3929.64 h60
  text "X" at 13275,3930 h60
  text "DRILLING:" at 11332.46,3790.64 h60
  text "REFERENCE:" at 11407.23,3673.64 h60
  text "X" at 12055.46,3673.64 h60
  text "AS SHOWN" at 12242.46,3673.64 h60
  text "X" at 12956.46,3673.64 h60
  text "NC_DRILL FILES" at 13093.46,3673.64 h60
  text "PTH MIN COPPER THICKNESS:" at 11407.23,3515.64 h60
  text "X" at 12757.46,3515.64 h60
  text "1MIL" at 12894.46,3515.64 h60
  text "OTHER" at 13391.46,3515.64 h60
  text "BOARD FINISH:" at 11332.46,3356.64 h60
  text "SILKSCREEN:" at 11487.68,3238.64 h60
  text "X" at 12436.46,3238.64 h60
  text "TOP" at 12562.46,3238.64 h60
  text "BOTTOM" at 13073.46,3238.64 h60
  text "SILKSCREEN COLOR:" at 11487.68,3071.64 h60
  text "X" at 12435.42,3071.64 h60
  text "WHITE" at 12562.46,3071.64 h60
  text "OTHER" at 13073.46,3071.64 h60
  text "SOLDER RESIST COLOR:" at 11487.68,2901.64 h60
  text "X" at 12055.42,2742.44 h60
  text "GREEN" at 12182.46,2742.44 h60
  text "BLUE" at 12773.46,2742.44 h60
  text "OTHER" at 13311.46,2742.44 h60
  text "IMMERSION GOLD (ENIG)" at 12393.46,2553.92 h60
  text "SURFACE FINISH:" at 11332.46,2549.64 h60
  text "Pb-FREE HASL" at 13625.75,2549.64 h60
  text "OTHER" at 12393.46,2392.64 h60
  text "X" at 12205,2390 h60
  text "IMMERSION TIN/SILVER OR EQUIV" at 12735,2390 h60
  text "X" at 12200,2230 h60
  text "ARRAY/PANEL:" at 11332.46,2213.64 h60
  text "CUT AND TRIM PER MECH LAYER 1" at 12393.46,2209.35 h60
  text "N.C. ROUTE" at 12393.46,2057.64 h60
  text "X" at 13072.46,2057.64 h60
  text "V. SCORE" at 13259.46,2057.64 h60
  text "CERTIFICATION:" at 11332.46,1920.64 h60
  text "MATERIALS AND WORKMANSHIP FOR ALL PCBS" at 12057.46,1920.64 h60
  text "TO MEET OR EXCEED THE REQUIREMENTS OF:" at 12057.46,1822.64 h60
  text "X" at 11683.96,1686.13 h60
  text "ANSI IPC-A-600F CLASS ->" at 11822.96,1686.13 h60
  text "X" at 13462.02,1686.13 h60
  text "2" at 13580.96,1686.14 h60
  text "1" at 13265.96,1684.64 h60
  text "3" at 13934.96,1684.64 h60
  text "X" at 11686.02,1526.64 h60
  text "UL 94V-0" at 11822.96,1526.64 h60
  text "X" at 12498.02,1526.64 h60
  text "RoHS" at 12634.96,1526.64 h60
  text "OTHER" at 13279.36,1526.64 h60
  text "PER ORDER" at 13676.42,1526.64 h60
  text "ADDITIONAL REQUIREMENTS:" at 11332.46,1385.64 h60
  text "MICROSECTION:" at 11407.23,1270.64 h60
  text "YES" at 12312.96,1270.64 h60
  text "REQUIRED" at 13174.46,1114.49 h60
  text "BARE BOARD ELEC. TEST:" at 11407.23,1111.64 h60
  text "NONE" at 12712.96,1111.64 h60
  text "X" at 13047.46,1111.64 h60
  text "PER ORDER" at 13766.46,1111.64 h60
  text "X" at 13750,960 h60
  text "MANUFACTURER'S ID/LOGO:" at 11407.23,954.64 h60
  text "RAIL" at 12872.96,950.35 h60
  text "METAL" at 13364.77,950.35 h60
  text "SILK" at 13876.46,950.35 h60
  text ".Layer_Name" at 577,-858.49 h60
M11 Gerber Information:
  lines w10: -292,-930.17 6308,-930.17 ; -292,-726.83 6310,-726.83 ; -292,-523.5 -292,-1133.5 3713,-1133.5 6310,-1133.5 6310,-523.5 -291.5,-523.5 -291.5,-1133.5 1284,-1133.5 ; 2173,-1133.5 2173,-523.5 ; 3440,-726.83 3440,-523.5 ; 4280,-726.83 4280,-523.5 ; 4902,-1140 4902,-937.17
  text "ALL ARTWORK VIEWED FROM TOP SIDE" at -228.5,-655.67 h60
  text "BOARD #:" at 2248,-655.67 h60
  text ".PRJ_Number" at 2793.5,-655.67 h60
  text "REV:" at 3638,-655.67 h60
  text ".PCB_Rev" at 3929.5,-655.67 h60
  text "SVN REV:" at 4476,-655.67 h60
  text ".VersionControl_RevNumber" at 4982,-655.67 h60
  text "LAYER NAME =" at -228.5,-858.49 h60
  text "PLOT NAME =" at -228.5,-1064.34 h60
  text ".plot_File_Name" at 577,-1064.34 h60
  text "GENERATED    :" at 2250,-1064.34 h60
  text ".Print_Date" at 3119.5,-1064.34 h60
  text ".Print_Time" at 3848.5,-1064.34 h60
  text "TEXAS INSTRUMENTS" at 5113,-1064.34 h60
M12 Stackup:
  lines w8: 8425,6546.5 11185,6546.5 ; 8425,6702.1 11185,6702.1 ; 8365,5550 ccw(c8415,5550) 8415,5500 11195,5500 ccw(c11195,5550) 11245,5550 11245,6840 ccw(c11195,6840) 11195,6890 8415,6890 ccw(c8415,6840) 8365,6840 8365,5550
  text "Layer Stack Up Detail for: PWR555A_pcb.PcbDoc" at 8425,6752.05 h60
  text "Layer" at 8425,6644.1 h36
  text "Gerber" at 9410.72,6644.1 h36
  text "Copper" at 9917.01,6644.1 h36
  text "Dielectric" at 10482.07,6644.1 h36
  text "Name" at 8425,6572.1 h36
  text "Document" at 9410.72,6572.1 h36
  text "Thickness" at 9917.01,6572.1 h36
  text "Material" at 10482.07,6572.1 h36
  text "Top Solder Mask" at 8425,6470.1 h50
  text "(.GTS)" at 9410.72,6470.1 h50
  text "Solder Resist" at 10482.07,6470.1 h50
  text "Top Layer" at 8425,6325.31 h50
  text "(.GTL)" at 9410.72,6325.31 h50
  text "2.8mil" at 9917.01,6325.31 h50
  text "FR-4" at 10482.07,6252.92 h50
  text "MidLayer1" at 8425,6180.52 h50
  text "(.G1)" at 9410.72,6180.52 h50
  text "2.8mil" at 9917.01,6180.52 h50
  text "FR-4" at 10482.07,6108.13 h50
  text "MidLayer2" at 8425,6035.73 h50
  text "(.G2)" at 9410.72,6035.73 h50
  text "2.8mil" at 9917.01,6035.73 h50
  text "FR-4" at 10482.07,5963.33 h50
  text "Bottom Layer" at 8425,5890.94 h50
  text "(.GBL)" at 9410.72,5890.94 h50
  text "2.8mil" at 9917.01,5890.94 h50
  text "Bottom Solder Mask" at 8425,5746.15 h50
  text "(.GBS)" at 9410.72,5746.15 h50
  text "Solder Resist" at 10482.07,5746.15 h50
  text ".Layer_Name" at 577,-858.49 h60
M13 Component Bodies Top:
  text ".Layer_Name" at 577,-858.49 h60
M14 Component Bodies Bottom:
  text ".Layer_Name" at 577,-858.49 h60
M15 Courtyards Top:
  lines w3.94: 1615.32,1260 1654.68,1260 ; 1635,1240.32 1635,1279.68 ; 1544.45,1175.35 1725.55,1175.35 1725.55,1344.65 1544.45,1344.65 1544.45,1175.35
  text ".Layer_Name" at 577,-858.49 h60
M16 Courtyards Bottom:
  text ".Layer_Name" at 577,-858.49 h60
Drill Drawing:
  text ".legend" at 3895,1000 h60
  text "Drill Table" at 3890,875 h60
  text ".Layer_Name" at 577,-858.49 h60

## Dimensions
0,0 to 0,3000 on M2 Board Dimensions
0,0 to 3000,0 on M2 Board Dimensions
